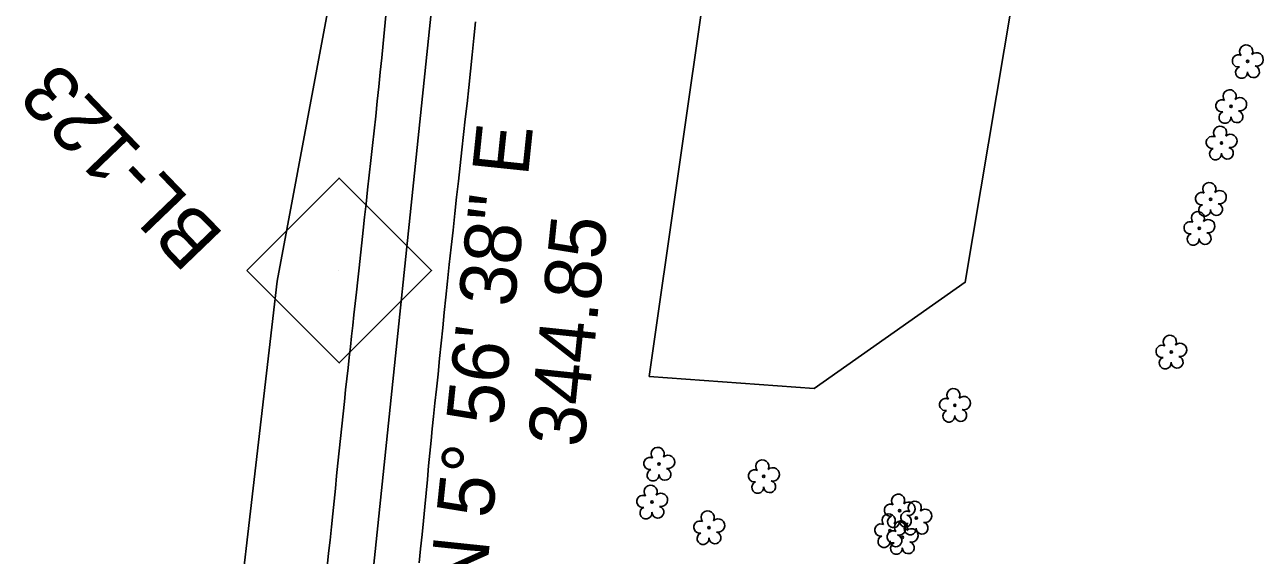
# Model space of a CAD drawing. Extents: x 473158 to 477500, y 500738 to 505114.
# Drawn here: x 474388.1 to 474739.8, y 504009.5 to 504160.1 of the extents above; entities that cross this region are included whole.
import ezdxf

# ---------------------------------------------------------------- set-up
doc = ezdxf.new("R2010")
doc.units = 0
for name, color, linetype in [('CTL Secondary Horizontal and Vertical CELL', 7, 'Continuous'), ('CTL Secondary Horizontal and Vertical Text', 7, 'Continuous'), ('Exist Horizontal Alignment', 7, 'Continuous'), ('Exist Horizontal Alignment Direction Label', 7, 'Continuous'), ('Exist Roads EOP', 7, 'Continuous'), ('Exist Vegetation Tree CELL', 7, 'Continuous'), ('Exist Vegetation Woods Line', 7, 'Continuous')]:
    doc.layers.add(name, color=color, linetype=linetype)

msp = doc.modelspace()

# ---------------------------------------------------------------- linework, layer by layer
at = {"layer": 'CTL Secondary Horizontal and Vertical CELL'}
msp.add_line((474477.2, 504090.28), (474477.2, 504090.28), dxfattribs=at)
msp.add_lwpolyline([(474451.13, 504090.37), (474477.34, 504116.58), (474503.59, 504090.33), (474477.38, 504064.12)], close=True, dxfattribs=at)
at = {"layer": 'Exist Horizontal Alignment'}
msp.add_line((474477.6, 503915.15), (474513.31, 504258.14), dxfattribs=at)
at = {"layer": 'Exist Roads EOP'}
for points in [[(474473.96, 504006.29), (474474.36, 504010.09), (474474.75, 504013.85), (474475.14, 504017.57), (474475.53, 504021.25), (474475.91, 504024.89), (474476.28, 504028.5), (474476.64, 504032.08), (474476.99, 504035.63), (474477.34, 504039.16), (474477.7, 504042.68), (474478.07, 504046.19), (474478.45, 504049.7), (474478.83, 504053.13), (474479.19, 504056.44), (474479.55, 504059.63), (474479.89, 504062.69), (474480.23, 504065.69), (474480.56, 504068.69), (474480.9, 504071.69), (474481.22, 504074.69), (474481.55, 504077.75), (474481.9, 504080.93), (474482.25, 504084.23), (474482.62, 504087.64), (474482.99, 504091.12), (474483.38, 504094.64), (474483.77, 504098.19), (474484.17, 504101.77), (474484.58, 504105.44), (474485, 504109.26), (474485.44, 504113.24), (474485.9, 504117.36), (474486.36, 504121.56), (474486.82, 504125.76), (474487.28, 504129.96), (474487.73, 504134.16), (474488.18, 504138.34), (474488.62, 504142.49), (474489.04, 504146.61), (474489.44, 504150.7), (474489.84, 504154.74), (474490.23, 504158.74), (474490.63, 504162.67)], [(474516.07, 504160.92), (474515.61, 504156.26), (474515.14, 504151.56), (474514.66, 504146.86), (474514.18, 504142.26), (474513.68, 504137.75), (474513.18, 504133.32), (474512.67, 504128.93), (474512.18, 504124.53), (474511.69, 504120.11), (474511.2, 504115.68), (474510.72, 504111.17), (474510.21, 504106.54), (474509.69, 504101.79), (474509.14, 504096.91), (474508.61, 504092.05), (474508.11, 504087.34), (474507.64, 504082.8), (474507.2, 504078.41), (474506.78, 504074.09), (474506.34, 504069.75), (474505.89, 504065.37), (474505.43, 504060.96), (474504.98, 504056.67), (474504.56, 504052.66), (474504.17, 504048.92), (474503.8, 504045.45), (474503.45, 504042.06), (474503.11, 504038.52), (474502.76, 504034.86), (474502.41, 504031.06), (474502.05, 504027.18), (474501.68, 504023.27), (474501.3, 504019.34), (474500.9, 504015.39), (474500.49, 504011.39), (474500.08, 504007.35)]]:
    msp.add_lwpolyline(points, dxfattribs=at)
at = {"layer": 'Exist Vegetation Tree CELL'}
for p, q in [((474735.34, 504149.65), (474735.34, 504149.65)), ((474730.64, 504136.9), (474730.64, 504136.9)), ((474727.94, 504126.53), (474727.94, 504126.53)), ((474724.85, 504110.56), (474724.85, 504110.56)), ((474721.61, 504102.32), (474721.61, 504102.32)), ((474713.65, 504067.23), (474713.65, 504067.23)), ((474652.2, 504052.11), (474652.2, 504052.11)), ((474568.19, 504035.41), (474568.19, 504035.41)), ((474597.92, 504031.89), (474597.92, 504031.89)), ((474566.19, 504024.66), (474566.19, 504024.66)), ((474636.5, 504022.15), (474636.5, 504022.15)), ((474641.23, 504020.13), (474641.23, 504020.13)), ((474582.39, 504017.39), (474582.39, 504017.39)), ((474633.79, 504016.54), (474633.79, 504016.54)), ((474637.3, 504014.58), (474637.3, 504014.58))]:
    msp.add_line(p, q, dxfattribs=at)
for centre in [(474735.34, 504149.65), (474730.64, 504136.9), (474727.94, 504126.53), (474724.85, 504110.56), (474721.61, 504102.32), (474713.65, 504067.23), (474652.2, 504052.11), (474568.19, 504035.41), (474597.92, 504031.89), (474566.19, 504024.66), (474636.5, 504022.15), (474641.23, 504020.13), (474582.39, 504017.39), (474633.79, 504016.54), (474637.3, 504014.58)]:
    msp.add_circle(centre, 0.326, dxfattribs=at)
for centre, radius, start, end in [((474734.95, 504152.53), 1.86, 330.1651, 219.7134), ((474732.73, 504149.81), 1.73, 62.6636, 279.3457), ((474737.89, 504150.24), 1.9, 257.1011, 134.1999), ((474733.64, 504146.53), 1.69, 111.5671, 6.231), ((474737.01, 504146.76), 1.7, 181.2822, 74.56), ((474728.03, 504137.05), 1.73, 62.6636, 279.3457), ((474730.25, 504139.77), 1.86, 330.1651, 219.7134), ((474733.18, 504137.49), 1.9, 257.1011, 134.1999), ((474728.93, 504133.78), 1.69, 111.5671, 6.231), ((474732.31, 504134), 1.7, 181.2822, 74.56), ((474725.33, 504126.69), 1.73, 62.6636, 279.3457), ((474727.55, 504129.41), 1.86, 330.1651, 219.7134), ((474730.49, 504127.12), 1.9, 257.1011, 134.1999), ((474726.23, 504123.41), 1.69, 111.5671, 6.231), ((474729.61, 504123.63), 1.7, 181.2822, 74.56), ((474724.47, 504113.44), 1.86, 330.1651, 219.7134), ((474722.25, 504110.72), 1.73, 62.6636, 279.3457), ((474727.4, 504111.15), 1.9, 257.1011, 134.1999), ((474723.15, 504107.44), 1.69, 111.5671, 6.231), ((474726.52, 504107.66), 1.7, 181.2822, 74.56), ((474719.01, 504102.48), 1.73, 62.6636, 279.3457), ((474721.23, 504105.2), 1.86, 330.1651, 219.7134), ((474724.16, 504102.91), 1.9, 257.1011, 134.1999), ((474719.91, 504099.2), 1.69, 111.5671, 6.231), ((474723.28, 504099.43), 1.7, 181.2822, 74.56), ((474713.27, 504070.11), 1.86, 330.1651, 219.7134), ((474711.05, 504067.39), 1.73, 62.6636, 279.3457), ((474716.2, 504067.82), 1.9, 257.1011, 134.1999), ((474711.95, 504064.11), 1.69, 111.5671, 6.231), ((474715.33, 504064.33), 1.7, 181.2822, 74.56), ((474651.81, 504054.99), 1.86, 330.1651, 219.7134), ((474654.74, 504052.7), 1.9, 257.1011, 134.1999), ((474649.59, 504052.27), 1.73, 62.6636, 279.3457), ((474653.87, 504049.21), 1.7, 181.2822, 74.56), ((474650.49, 504048.99), 1.69, 111.5671, 6.231), ((474565.59, 504035.57), 1.73, 62.6636, 279.3457), ((474567.81, 504038.29), 1.86, 330.1651, 219.7134), ((474570.74, 504036), 1.9, 257.1011, 134.1999), ((474566.49, 504032.29), 1.69, 111.5671, 6.231), ((474569.87, 504032.51), 1.7, 181.2822, 74.56), ((474595.32, 504032.04), 1.73, 62.6636, 279.3457), ((474597.54, 504034.76), 1.86, 330.1651, 219.7134), ((474600.47, 504032.47), 1.9, 257.1011, 134.1999), ((474596.22, 504028.77), 1.69, 111.5671, 6.231), ((474599.6, 504028.99), 1.7, 181.2822, 74.56), ((474563.58, 504024.81), 1.73, 62.6636, 279.3457), ((474565.8, 504027.53), 1.86, 330.1651, 219.7134), ((474568.73, 504025.25), 1.9, 257.1011, 134.1999), ((474636.11, 504025.03), 1.86, 330.1651, 219.7134), ((474564.48, 504021.54), 1.69, 111.5671, 6.231), ((474567.86, 504021.76), 1.7, 181.2822, 74.56), ((474633.89, 504022.31), 1.73, 62.6636, 279.3457), ((474639.04, 504022.74), 1.9, 257.1011, 134.1999), ((474640.84, 504023.01), 1.86, 330.1651, 219.7134), ((474579.79, 504017.54), 1.73, 62.6636, 279.3457), ((474582.01, 504020.26), 1.86, 330.1651, 219.7134), ((474584.94, 504017.98), 1.9, 257.1011, 134.1999), ((474633.4, 504019.41), 1.86, 330.1651, 219.7134), ((474634.79, 504019.03), 1.69, 111.5671, 6.231), ((474636.92, 504017.45), 1.86, 330.1651, 219.7134), ((474638.17, 504019.25), 1.7, 181.2822, 74.56), ((474638.62, 504020.29), 1.73, 62.6636, 279.3457), ((474643.77, 504020.72), 1.9, 257.1011, 134.1999), ((474580.69, 504014.27), 1.69, 111.5671, 6.231), ((474584.07, 504014.49), 1.7, 181.2822, 74.56), ((474631.18, 504016.69), 1.73, 62.6636, 279.3457), ((474634.7, 504014.73), 1.73, 62.6636, 279.3457), ((474636.34, 504017.13), 1.9, 257.1011, 134.1999), ((474639.52, 504017.01), 1.69, 111.5671, 6.231), ((474639.85, 504015.17), 1.9, 257.1011, 134.1999), ((474642.9, 504017.23), 1.7, 181.2822, 74.56), ((474632.08, 504013.42), 1.69, 111.5671, 6.231), ((474635.46, 504013.64), 1.7, 181.2822, 74.56), ((474635.6, 504011.46), 1.69, 111.5671, 6.231), ((474638.97, 504011.68), 1.7, 181.2822, 74.56)]:
    msp.add_arc(centre, radius, start, end, dxfattribs=at)
at = {"layer": 'Exist Vegetation Woods Line'}
for points in [[(474494.78, 504312.62), (474476.79, 504178.44), (474459.77, 504087.31), (474441.83, 503933.16), (474440.33, 503857.37), (474437.89, 503709.04), (474417.41, 503659.72)], [(474598.56, 504291.71), (474683.89, 504258.46), (474655.17, 504086.99), (474612.22, 504056.82), (474565.4, 504060.3), (474598.56, 504291.71)]]:
    msp.add_lwpolyline(points, dxfattribs=at)

# ---------------------------------------------------------------- texts
at = {"layer": 'CTL Secondary Horizontal and Vertical Text'}
msp.add_text('BL-123', height=16, rotation=133.8723, dxfattribs=at).set_placement((474445.04, 504100.36))
at = {"layer": 'Exist Horizontal Alignment Direction Label'}
for s, p in [('N 5%%d 56\' 38" E', (474518.64, 503998.48)), ('344.85', (474546.84, 504039.87))]:
    msp.add_text(s, height=16, rotation=84.0561, dxfattribs=at).set_placement(p)

doc.saveas('drawing.dxf')
